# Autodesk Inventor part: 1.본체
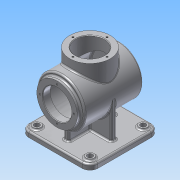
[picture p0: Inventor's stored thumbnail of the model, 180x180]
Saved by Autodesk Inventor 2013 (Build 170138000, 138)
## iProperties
Created: 2015-07
Part Number: 1.본체
Material: 알루미늄 6061
Document SubType Name: Modeling
Designer: Administrator
Density: 2.71 g/cm^3
Mass: 1372.97 g
Surface Area: 1250.05 cm^2
Volume: 506.633 cm^3
Author: Administrator
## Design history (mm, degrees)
sketch "스케치1"
  geometry: L1 (-50, 65)-(50, 65); L2 (65, 50)-(65, -50); L3 (50, -65)-(-50, -65); L4 (-65, -50)-(-65, 50); A1 r 15 centre (50, 50) between (65, 50) and (50, 65); A2 r 15 centre (50, -50) between (50, -65) and (65, -50); A3 r 15 centre (-50, -50) between (-65, -50) and (-50, -65); A4 r 15 centre (-50, 50) between (-50, 65) and (-65, 50); 3 further points
  constraints: 8 end point, 8 point on circle, 8 tangent, 4 centre point, 3 equal radius, 2 midpoint, 2 parallel, 2 perpendicular, 1 horizontal, 1 horizontal alignment, 1 vertical alignment
  dimensions: "d1" = 130 distance between parallel lines of L2 L4; "d3" = 15 radius of A1
extrude "돌출1" new body sketch "스케치1" distance "d4" = 10; taper "d5" = 0 deg
sketch "스케치2"
  geometry: L1 (-50, 0)-(50, 0) reference; C1 r 45 at (0, 78); 2 further points
  constraints: 1 centre point, 1 midpoint, 1 vertical alignment
  dimensions: "d6" = 78 distance from line of C1.centre L1; "d7" = 90 diameter of C1
extrude "돌출2" join sketch "스케치2" stored distance "d8" = 110; taper "d9" = 0 deg
sketch "스케치3"
  geometry: L1 (50, -78)-(-50, -78) reference; C1 r 45 at (0, 0) reference; C2 r 38 at (0, 0); 1 further point
  constraints: 1 centre point, 1 coincident
  dimensions: "d10" = 76 diameter of C2
extrude "돌출3" join sketch "스케치3" distance "d12" = 7; taper "d13" = 0 deg
node "작업 평면1"
sketch "스케치5"
  geometry: C1 r 38 at (0, 0); 1 further point
  constraints: 1 centre point, 1 coincident
  dimensions: "d15" = 76 diameter of C1
extrude "돌출4" join sketch "스케치5" distance "d17" = 62; taper "d18" = 0 deg
sketch "스케치7"
  geometry: C1 r 27 at (0, 0); 1 further point
  constraints: 1 centre point, 1 coincident
  dimensions: "d24" = 54 diameter of C1
extrude "돌출5" cut sketch "스케치7" distance "d26" = 62; taper "d27" = 0 deg
sketch "스케치8" dims "d28" = 64
  geometry: 3 further points
  constraints: 2 horizontal alignment, 1 coincident, 2 other
hole "구멍1" sketch "스케치8" at (-32, 0) diameter "d30" = 3.242; stored, may be unused: countersink angle "d34" = 90 deg, drill point angle "d36" = 118 deg; dims "d31" = 8, "d32" = 4, "d33" = 2, "d35" = 10
sketch "스케치9"
  geometry: L1 (-5, 45)-(5, 45); L2 (5, -45)-(-5, -45); L3 (45, 5)-(45, -5); L4 (-45, -5)-(-45, 5); L5 (5, 45)-(5, 5); L6 (5, -5)-(5, -45); L7 (-45, 5)-(-5, 5); L8 (5, 5)-(45, 5); L9 (-5, -45)-(-5, -5); L10 (-5, 5)-(-5, 45); L11 (45, -5)-(5, -5); L12 (-5, -5)-(-45, -5); 3 further points
  constraints: 24 end point, 10 parallel, 4 collinear, 4 perpendicular, 3 horizontal, 2 midpoint, 1 horizontal alignment, 1 vertical alignment
  dimensions: "d40" = 10 distance between parallel lines of L5 L10; "d42" = 10 distance between parallel lines of L11 L8; "d43" = 90 distance between parallel lines of L3 L4; "d44" = 90 distance between parallel lines of L2 L1; "d45" = 45 distance from line of L3 point (0, 0); "d46" = 45 distance from line of L2 point (0, 0)
extrude "돌출6" join sketch "스케치9" distance "d47" = 68; taper "d48" = 0 deg
sketch "스케치10"
  geometry: L1 (-62, 116)-(-62, 40) reference; L2 (55, 33)-(55, 123) reference; L3 (-62, 78)-(41, 78); L4 (-62, 105)-(-48, 105); L5 (-48, 105)-(-48, 118); L6 (-48, 118)-(41, 118); L7 (41, 118)-(41, 78); 1 further point
  constraints: 10 end point, 2 parallel, 2 perpendicular, 1 midpoint, 1 point on line
  dimensions: "d49" = 14 distance between parallel lines of L2 L7; "d50" = 54 diameter of L4 L3; "d51" = 80 diameter of L6 L3; "d52" = 14 distance between parallel lines of L5 L1
revolve "회전2" sketch "스케치10" stored, may be unused: angle "d53" = 90 deg
sketch "스케치11" dims "d54" = 64
  geometry: C1 r 38 at (0, 0) reference; 3 further points
  constraints: 2 vertical alignment, 1 coincident, 2 other
hole "구멍2" sketch "스케치11" at (0, 32) diameter "d56" = 3.242; stored, may be unused: countersink angle "d60" = 90 deg, drill point angle "d62" = 118 deg; dims "d57" = 8, "d58" = 4, "d59" = 2, "d61" = 10
sketch "스케치12"
  geometry: C1 r 7.5 at (50, 50); C2 r 7.5 at (-50, 50); C3 r 7.5 at (-50, -50); C4 r 7.5 at (50, -50); 1 further point
  constraints: 4 centre point, 3 equal radius, 2 horizontal alignment, 2 vertical alignment
  dimensions: "d66" = 100 distance of C4.centre C1.centre; "d68" = 100 distance of C1.centre C2.centre; "d69" = 50 horizontal distance of C1.centre point (0, 0); "d70" = 50 horizontal distance of C1.centre point (0, 0); "d71" = 15 diameter of C2
extrude "돌출7" join sketch "스케치12" distance "d74" = 3; taper "d75" = 0 deg
hole "구멍3" diameter "d78" = 10; stored, may be unused: countersink angle "d82" = 90 deg, drill point angle "d84" = 118 deg; dims "d76" = 10, "d77" = 10, "d79" = 10, "d80" = 4, "d81" = 2, "d83" = 10
hole "구멍4" diameter "d87" = 10; stored, may be unused: countersink angle "d91" = 90 deg, drill point angle "d93" = 118 deg; dims "d85" = 10, "d86" = 10, "d88" = 10, "d89" = 4, "d90" = 2, "d92" = 10
hole "구멍5" diameter "d96" = 10; stored, may be unused: countersink angle "d100" = 90 deg, drill point angle "d102" = 118 deg; dims "d94" = 10, "d95" = 10, "d97" = 10, "d98" = 4, "d99" = 2, "d101" = 10
hole "구멍6" diameter "d105" = 10; stored, may be unused: countersink angle "d109" = 90 deg, drill point angle "d111" = 118 deg; dims "d103" = 10, "d104" = 10, "d106" = 10, "d107" = 4, "d108" = 2, "d110" = 10
sketch "스케치14"
  geometry: L1 (24.887, -3.602)-(-24.887, -3.602); L2 (-24.887, -3.602)-(-24.887, 3.602); L3 (-24.887, 3.602)-(24.887, 3.602); L4 (24.887, 3.602)-(24.887, -3.602); A1 r 45 centre (0, 0) between (45, 0) and (5, 44.721) reference; A2 r 45 centre (0, 0) between (5, 44.721) and (-5, 44.721) reference; A3 r 45 centre (0, 0) between (-5, 44.721) and (-45, 0) reference; A4 r 45 centre (0, 0) between (45, 0) and (5, 44.721) reference; 6 further points
  constraints: 4 midpoint, 2 horizontal alignment, 2 vertical alignment, 1 coincident, 2 other
feature "엠보싱1" sketch "스케치14" dims "d112" = 0.5, "d113" = 0
chamfer "모따기1" distance "d114" = 1; stored, may be unused: second distance "d115" = 2, angle "d116" = 45 deg
fillet "모깎기1" dims "d117" = 3
fillet "모깎기2" dims "d118" = 3
fillet "모깎기3" dims "d119" = 3
fillet "모깎기4" dims "d120" = 3
fillet "모깎기5" dims "d121" = 3
fillet "모깎기6" dims "d122" = 3
fillet "모깎기7" dims "d123" = 3
fillet "모깎기8" dims "d124" = 3
node "솔리드1"
pattern_circular "원형 패턴1" dims angle "d38" = 360 deg
pattern_circular "원형 패턴2" dims angle "d64" = 360 deg
other parameters: "d14" = 78
